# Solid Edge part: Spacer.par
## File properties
Author: CADCIM
Template: NORMENG.PAR
Last saved by: CADCIM
Revision: 3
Application: Solid Edge
Density: 0 lbm/in^3
Accuracy: 0.99
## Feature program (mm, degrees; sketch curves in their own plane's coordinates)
sketch for "unnamed Protrusion 1" #1 plane through (0, 0, 0) normal (0, 0, 1) x-axis (1, 0, 0)
  circle centre (0, 0) radius 15.875
sketch for "unnamed Protrusion 1" #2 plane through (0, 0, 0) normal (0, 0, 1) x-axis (1, 0, 0)
  circle centre (0, 0) radius 12.7
extrude "unnamed Protrusion 1" add finite 34.925 symmetric
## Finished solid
Body 1: solid body, 4 faces, 4 edges, 0 vertices.
  Faces by surface: cylinder 2, plane 2
  Edges by curve: circle 4
Bounding box of the edges (mm): 31.750 x 31.750 x 34.925, from (-15.875, -15.875, -17.4625) to (15.875, 15.875, 17.4625).
Cylindrical faces by radius (mm): R12.7 x1, R15.875 x1
Planar faces by outward normal: +z 1, -z 1
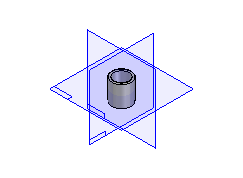
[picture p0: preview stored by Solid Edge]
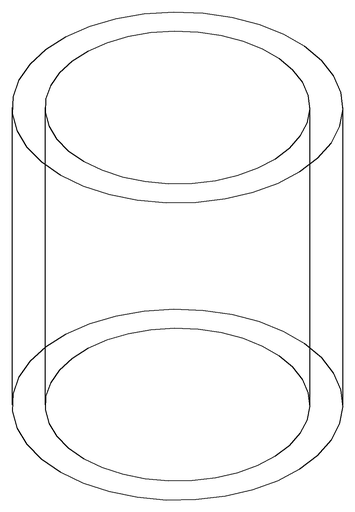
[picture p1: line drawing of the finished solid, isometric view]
